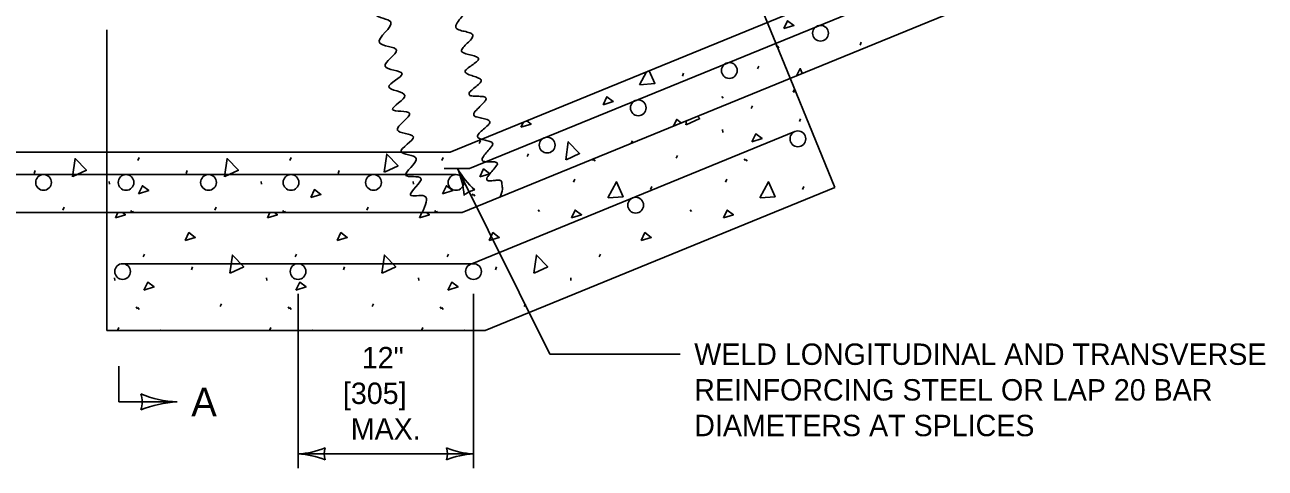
# Model space of a CAD drawing. Extents: x 49991.4 to 50021, y 49987.6 to 50011.4.
# Drawn here: x 50003.206 to 50006.686, y 50002.268 to 50003.512 of the extents above; entities that cross this region are included whole.
import ezdxf

# ---------------------------------------------------------------- set-up
doc = ezdxf.new("R2010")
doc.units = 0
for name, color, linetype in [('Level 1', 7, 'Continuous'), ('Level 2', 7, 'Continuous'), ('Level 3', 7, 'Continuous'), ('Level 4', 7, 'Continuous'), ('Level 6', 7, 'Continuous')]:
    doc.layers.add(name, color=color, linetype=linetype)

msp = doc.modelspace()

# ---------------------------------------------------------------- linework, layer by layer
at = {"layer": 'Level 1'}
for p, q in [((50004.3994, 50003.1543), (50005.8839, 50003.7616)), ((50005.9077, 50003.7036), (50004.4541, 50003.109)), ((50004.4328, 50002.985), (50005.9481, 50003.6048)), ((50005.3138, 50003.4538), (50005.3174, 50003.4485)), ((50005.5492, 50003.4548), (50005.5528, 50003.4628)), ((50005.3184, 50003.4518), (50005.3219, 50003.4465)), ((50005.2614, 50003.388), (50005.265, 50003.396)), ((50005.0509, 50003.3676), (50005.0545, 50003.3756)), ((50005.3533, 50003.3615), (50005.4785, 50003.0556)), ((50005.1619, 50003.3107), (50005.1655, 50003.3054)), ((50005.2442, 50003.2766), (50005.2478, 50003.2846)), ((50005.3792, 50003.2402), (50005.3827, 50003.2482)), ((50005.3666, 50003.2124), (50004.4606, 50002.8417)), ((50005.1639, 50003.2179), (50005.1648, 50003.2099)), ((50004.4807, 50003.1784), (50004.4843, 50003.1864)), ((50004.9075, 50003.1793), (50004.9106, 50003.1864)), ((50002.7761, 50003.1543), (50004.3994, 50003.1543)), ((50004.6157, 50003.142), (50004.6192, 50003.15)), ((50005.0336, 50003.1372), (50005.0372, 50003.1452)), ((50003.5237, 50003.1312), (50003.5273, 50003.1392)), ((50003.9501, 50003.1312), (50003.9536, 50003.1392)), ((50004.3765, 50003.1312), (50004.38, 50003.1392)), ((50004.3823, 50003.109), (50004.4541, 50003.109)), ((50004.799, 50003.1349), (50004.8017, 50003.1309)), ((50004.8027, 50003.1342), (50004.8063, 50003.1289)), ((50005.2245, 50003.1362), (50005.2281, 50003.1309)), ((50005.2291, 50003.1342), (50005.2327, 50003.1289)), ((50002.7761, 50003.0917), (50004.416, 50003.0917)), ((50003.2323, 50003.0948), (50003.2359, 50003.1028)), ((50003.4434, 50003.0725), (50003.4443, 50003.0645)), ((50003.6587, 50003.0948), (50003.6622, 50003.1028)), ((50003.8698, 50003.0725), (50003.8707, 50003.0645)), ((50004.0851, 50003.0948), (50004.0886, 50003.1028)), ((50004.2962, 50003.0725), (50004.2971, 50003.0645)), ((50004.7458, 50003.0704), (50004.7493, 50003.0784)), ((50005.1721, 50003.0704), (50005.1757, 50003.0784)), ((50004.461, 50003.038), (50004.4646, 50003.0327)), ((50004.4656, 50003.036), (50004.4692, 50003.0306)), ((50004.4975, 50002.6543), (50005.4785, 50003.0556)), ((50004.9617, 50003.05), (50004.9652, 50003.058)), ((50005.3881, 50003.05), (50005.3916, 50003.058)), ((50002.7761, 50002.985), (50004.4328, 50002.985)), ((50003.3131, 50002.9918), (50003.3167, 50002.9998)), ((50003.4365, 50002.985), (50003.4365, 50002.6543)), ((50003.504, 50002.9908), (50003.5076, 50002.9855)), ((50003.5086, 50002.9888), (50003.5111, 50002.985)), ((50003.7395, 50002.9918), (50003.743, 50002.9998)), ((50003.9304, 50002.9908), (50003.934, 50002.9855)), ((50003.935, 50002.9888), (50003.9375, 50002.985)), ((50004.1659, 50002.9918), (50004.1694, 50002.9998)), ((50004.3568, 50002.9908), (50004.3604, 50002.9855)), ((50004.3614, 50002.9888), (50004.3639, 50002.985)), ((50004.6463, 50002.9931), (50004.6499, 50002.9878)), ((50005.0727, 50002.9931), (50005.0762, 50002.9878)), ((50003.5387, 50002.8608), (50003.5423, 50002.8688)), ((50003.9651, 50002.8608), (50003.9686, 50002.8688)), ((50004.3915, 50002.8608), (50004.395, 50002.8688)), ((50004.8178, 50002.8608), (50004.8214, 50002.8688)), ((50003.4807, 50002.8417), (50004.4606, 50002.8417)), ((50003.6737, 50002.8244), (50003.6772, 50002.8324)), ((50004.1001, 50002.8244), (50004.1036, 50002.8324)), ((50004.5264, 50002.8244), (50004.53, 50002.8324)), ((50003.4584, 50002.8021), (50003.4593, 50002.7941)), ((50003.8848, 50002.8021), (50003.8857, 50002.7941)), ((50004.3112, 50002.8021), (50004.3121, 50002.7941)), ((50004.7376, 50002.8021), (50004.7384, 50002.7941)), ((50003.7545, 50002.7214), (50003.758, 50002.7294)), ((50004.1809, 50002.7214), (50004.1844, 50002.7294)), ((50004.6072, 50002.7214), (50004.6108, 50002.7294)), ((50003.519, 50002.7204), (50003.5226, 50002.7151)), ((50003.5236, 50002.7184), (50003.5272, 50002.713)), ((50003.9454, 50002.7204), (50003.949, 50002.7151)), ((50003.95, 50002.7184), (50003.9535, 50002.713)), ((50004.3718, 50002.7204), (50004.3754, 50002.7151)), ((50004.3764, 50002.7184), (50004.3799, 50002.713)), ((50003.4365, 50002.6543), (50004.4975, 50002.6543)), ((50003.4666, 50002.6546), (50003.4702, 50002.6626)), ((50003.893, 50002.6546), (50003.8966, 50002.6626)), ((50004.3194, 50002.6546), (50004.323, 50002.6626))]:
    msp.add_line(p, q, dxfattribs=at)
for points in [[(50005.3352, 50003.501), (50005.3459, 50003.5232), (50005.3636, 50003.5099), (50005.3352, 50003.501)], [(50005.3707, 50003.3688), (50005.3814, 50003.3889), (50005.3874, 50003.3756)], [(50004.9311, 50003.3436), (50004.9501, 50003.3796)], [(50004.9578, 50003.3827), (50004.9737, 50003.3471), (50004.9319, 50003.3436)], [(50005.3616, 50003.3224), (50005.3658, 50003.3311)], [(50005.3685, 50003.3245), (50005.3616, 50003.3224)], [(50004.8288, 50003.2876), (50004.8395, 50003.3098), (50004.8572, 50003.2965), (50004.8288, 50003.2876)], [(50005.0263, 50003.2279), (50005.0351, 50003.2464), (50005.0479, 50003.2367)], [(50005.0935, 50003.2553), (50005.0997, 50003.2489), (50005.0617, 50003.2313)], [(50004.6143, 50003.2422), (50004.6265, 50003.233), (50004.5981, 50003.2242)], [(50004.5981, 50003.2242), (50004.6049, 50003.2384)], [(50005.0608, 50003.231), (50005.0624, 50003.2426)], [(50004.7237, 50003.1328), (50004.7308, 50003.1836), (50004.7626, 50003.1507), (50004.7246, 50003.1331)], [(50005.246, 50003.1834), (50005.2566, 50003.2056), (50005.2744, 50003.1923), (50005.246, 50003.1834)], [(50004.2149, 50003.0984), (50004.2219, 50003.1492), (50004.2537, 50003.1163), (50004.2157, 50003.0987)], [(50003.3403, 50003.0856), (50003.3474, 50003.1364), (50003.3792, 50003.1035), (50003.3412, 50003.0859)], [(50003.7667, 50003.0856), (50003.7738, 50003.1364), (50003.8056, 50003.1035), (50003.7676, 50003.0859)], [(50004.4825, 50003.0852), (50004.4931, 50003.1074), (50004.5109, 50003.0941), (50004.4825, 50003.0852)], [(50004.8418, 50003.026), (50004.8658, 50003.0713), (50004.8844, 50003.0295), (50004.8427, 50003.026)], [(50005.2682, 50003.026), (50005.2922, 50003.0713), (50005.3108, 50003.0295), (50005.2691, 50003.026)], [(50003.5255, 50003.038), (50003.5361, 50003.0602), (50003.5539, 50003.0469), (50003.5255, 50003.038)], [(50004.0084, 50003.0271), (50004.019, 50003.0493), (50004.0368, 50003.036), (50004.0084, 50003.0271)], [(50004.3782, 50003.038), (50004.3889, 50003.0602), (50004.4066, 50003.0469), (50004.3782, 50003.038)], [(50003.4604, 50002.97), (50003.4676, 50002.985)], [(50003.4807, 50002.985), (50003.4888, 50002.9789), (50003.4604, 50002.97)], [(50003.8868, 50002.97), (50003.894, 50002.985)], [(50003.9071, 50002.985), (50003.9152, 50002.9789), (50003.8868, 50002.97)], [(50004.3132, 50002.97), (50004.3204, 50002.985)], [(50004.3334, 50002.985), (50004.3416, 50002.9789), (50004.3132, 50002.97)], [(50004.7396, 50002.97), (50004.7502, 50002.9922), (50004.768, 50002.9789), (50004.7396, 50002.97)], [(50005.1659, 50002.97), (50005.1766, 50002.9922), (50005.1943, 50002.9789), (50005.1659, 50002.97)], [(50003.6561, 50002.9066), (50003.6668, 50002.9288), (50003.6845, 50002.9154), (50003.6561, 50002.9066)], [(50004.0825, 50002.9066), (50004.0931, 50002.9288), (50004.1109, 50002.9154), (50004.0825, 50002.9066)], [(50004.5088, 50002.9066), (50004.5195, 50002.9288), (50004.5373, 50002.9154), (50004.5088, 50002.9066)], [(50004.9352, 50002.9066), (50004.9459, 50002.9288), (50004.9636, 50002.9154), (50004.9352, 50002.9066)], [(50003.7817, 50002.8152), (50003.7888, 50002.866), (50003.8206, 50002.8331), (50003.7826, 50002.8155)], [(50004.2081, 50002.8152), (50004.2151, 50002.866), (50004.2469, 50002.8331), (50004.2089, 50002.8155)], [(50004.6345, 50002.8152), (50004.6415, 50002.866), (50004.6733, 50002.8331), (50004.6353, 50002.8155)], [(50003.5405, 50002.7676), (50003.5511, 50002.7898), (50003.5689, 50002.7765), (50003.5405, 50002.7676)], [(50003.9669, 50002.7676), (50003.9775, 50002.7898), (50003.9953, 50002.7765), (50003.9669, 50002.7676)], [(50004.3932, 50002.7676), (50004.4039, 50002.7898), (50004.4216, 50002.7765), (50004.3932, 50002.7676)], [(50003.5861, 50002.6543), (50003.5867, 50002.6555), (50003.5872, 50002.6543)], [(50004.0124, 50002.6543), (50004.013, 50002.6555), (50004.0135, 50002.6543)], [(50004.4388, 50002.6543), (50004.4394, 50002.6555), (50004.4399, 50002.6543)]]:
    msp.add_lwpolyline(points, dxfattribs=at)
for centre in [(50005.4384, 50003.488), (50005.1828, 50003.3834), (50004.9272, 50003.2788), (50005.375, 50003.1919), (50004.6716, 50003.1742), (50003.259, 50003.0696), (50003.4904, 50003.0696), (50003.7218, 50003.0696), (50003.9532, 50003.0696), (50004.1846, 50003.0696), (50004.416, 50003.0696), (50004.92, 50003.0057), (50003.4807, 50002.8196), (50003.9729, 50002.8196), (50004.4651, 50002.8196)]:
    msp.add_circle(centre, 0.0221, dxfattribs=at)
for points in [[(50004.173, 50004.8655), (50004.1642, 50004.8559), (50004.1602, 50004.8397), (50004.1602, 50004.8228), (50004.1622, 50004.8103), (50004.1697, 50004.8052), (50004.184, 50004.8024), (50004.1986, 50004.7996), (50004.204, 50004.7975), (50004.2071, 50004.7944), (50004.2035, 50004.7841), (50004.1908, 50004.7717), (50004.1776, 50004.7595), (50004.1736, 50004.7541), (50004.1728, 50004.7496), (50004.1755, 50004.7464), (50004.181, 50004.744), (50004.1965, 50004.7402), (50004.2121, 50004.7365), (50004.2176, 50004.7342), (50004.2193, 50004.7327), (50004.2203, 50004.7311), (50004.2204, 50004.729), (50004.2154, 50004.7211), (50004.2017, 50004.7087), (50004.1881, 50004.6962), (50004.1841, 50004.6908), (50004.1833, 50004.6862), (50004.1859, 50004.6836), (50004.191, 50004.6821), (50004.2057, 50004.6807), (50004.2203, 50004.6794), (50004.2256, 50004.678), (50004.2282, 50004.6757), (50004.2242, 50004.6661), (50004.2123, 50004.6533), (50004.2005, 50004.6404), (50004.197, 50004.635), (50004.1965, 50004.6308), (50004.1974, 50004.6296), (50004.2044, 50004.6277), (50004.2192, 50004.6275), (50004.2338, 50004.627), (50004.2389, 50004.6256), (50004.2405, 50004.6244), (50004.2414, 50004.6229), (50004.2406, 50004.6183), (50004.2369, 50004.6131), (50004.2244, 50004.6017), (50004.2118, 50004.5903), (50004.208, 50004.5852), (50004.2071, 50004.5807), (50004.208, 50004.5787), (50004.2148, 50004.5732), (50004.2296, 50004.5662), (50004.2443, 50004.5593), (50004.2494, 50004.5556), (50004.2519, 50004.5516), (50004.2471, 50004.5424), (50004.2346, 50004.5319), (50004.2222, 50004.5214), (50004.2184, 50004.5165), (50004.2176, 50004.5121), (50004.2201, 50004.5089), (50004.2252, 50004.5067), (50004.2399, 50004.5038), (50004.2547, 50004.5011), (50004.2599, 50004.499), (50004.2625, 50004.4962), (50004.2585, 50004.4857), (50004.2468, 50004.4723), (50004.235, 50004.459), (50004.2315, 50004.4533), (50004.2308, 50004.4487), (50004.2318, 50004.447), (50004.2394, 50004.4432), (50004.256, 50004.4397), (50004.2725, 50004.436), (50004.2782, 50004.4335), (50004.2801, 50004.432), (50004.281, 50004.4302), (50004.2799, 50004.4261), (50004.2756, 50004.4215), (50004.2614, 50004.4116), (50004.2471, 50004.4018), (50004.2427, 50004.3973), (50004.2414, 50004.3933), (50004.2439, 50004.3898), (50004.2493, 50004.3868), (50004.2651, 50004.3813), (50004.2809, 50004.3758), (50004.2864, 50004.3728), (50004.2889, 50004.3695), (50004.2836, 50004.3607), (50004.2701, 50004.35), (50004.2568, 50004.3391), (50004.2528, 50004.3342), (50004.2519, 50004.33), (50004.2546, 50004.3273), (50004.26, 50004.3257), (50004.2757, 50004.3247), (50004.2913, 50004.3237), (50004.2967, 50004.3221), (50004.2985, 50004.3209), (50004.2994, 50004.3194), (50004.2995, 50004.3172), (50004.2953, 50004.309), (50004.2835, 50004.2958), (50004.2717, 50004.2825), (50004.2683, 50004.2767), (50004.2678, 50004.2719), (50004.2688, 50004.27), (50004.2762, 50004.2654), (50004.2917, 50004.2603), (50004.3072, 50004.2551), (50004.3126, 50004.2519), (50004.3153, 50004.2481), (50004.3112, 50004.2383), (50004.2997, 50004.2268), (50004.288, 50004.2154), (50004.2844, 50004.2103), (50004.2836, 50004.2059), (50004.2861, 50004.2023), (50004.2912, 50004.1993), (50004.3061, 50004.1941), (50004.3209, 50004.1889), (50004.3261, 50004.1858), (50004.3285, 50004.1822), (50004.3284, 50004.18), (50004.3234, 50004.1728), (50004.3101, 50004.1623), (50004.2968, 50004.1519), (50004.2926, 50004.147), (50004.2915, 50004.1426), (50004.294, 50004.1388), (50004.2995, 50004.1354), (50004.3153, 50004.1296), (50004.3311, 50004.1236), (50004.3366, 50004.1202), (50004.339, 50004.1162), (50004.334, 50004.1069), (50004.3217, 50004.0965), (50004.3095, 50004.086), (50004.3057, 50004.0811), (50004.3047, 50004.0766), (50004.3073, 50004.0722), (50004.3128, 50004.0682), (50004.3286, 50004.0609), (50004.3443, 50004.0535), (50004.3497, 50004.0494), (50004.3522, 50004.0449), (50004.3472, 50004.0344), (50004.3348, 50004.0227), (50004.3225, 50004.0109), (50004.3187, 50004.0053), (50004.3179, 50004.0001), (50004.3189, 50003.9974), (50004.3265, 50003.9902), (50004.3428, 50003.9814), (50004.3593, 50003.9728), (50004.3651, 50003.9681), (50004.3681, 50003.9631), (50004.3643, 50003.9516), (50004.3534, 50003.9382), (50004.3425, 50003.9246), (50004.3394, 50003.9184), (50004.339, 50003.913), (50004.3399, 50003.9111), (50004.3463, 50003.907), (50004.3599, 50003.9033), (50004.3736, 50003.8999), (50004.3786, 50003.8976), (50004.3812, 50003.8945), (50004.3777, 50003.8839), (50004.3667, 50003.8708), (50004.3556, 50003.8577), (50004.3525, 50003.8519), (50004.3522, 50003.847), (50004.3532, 50003.8454), (50004.3597, 50003.8419), (50004.3733, 50003.839), (50004.3869, 50003.8362), (50004.3918, 50003.8341), (50004.3944, 50003.8312), (50004.3909, 50003.8184), (50004.3787, 50003.8021), (50004.3664, 50003.7859), (50004.363, 50003.7788), (50004.3628, 50003.7731), (50004.3638, 50003.7715), (50004.3708, 50003.768), (50004.3853, 50003.7654), (50004.3997, 50003.7627), (50004.4049, 50003.7605), (50004.4076, 50003.7573), (50004.4038, 50003.7464), (50004.3921, 50003.7333), (50004.3802, 50003.7204), (50004.3767, 50003.7146), (50004.376, 50003.7098), (50004.3769, 50003.708), (50004.3837, 50003.7032), (50004.3984, 50003.6979), (50004.4131, 50003.6926), (50004.4182, 50003.6895), (50004.4208, 50003.686), (50004.4165, 50003.6775), (50004.4049, 50003.6676), (50004.3933, 50003.6577), (50004.3899, 50003.6531), (50004.3892, 50003.6491), (50004.3918, 50003.646), (50004.397, 50003.6439), (50004.4116, 50003.6411), (50004.4262, 50003.6384), (50004.4314, 50003.6362), (50004.434, 50003.6332), (50004.4303, 50003.6222), (50004.4192, 50003.6084), (50004.4083, 50003.5945), (50004.4052, 50003.5883), (50004.405, 50003.5831), (50004.406, 50003.5813), (50004.4126, 50003.577), (50004.4261, 50003.5726), (50004.4397, 50003.5682), (50004.4446, 50003.5654), (50004.4472, 50003.562), (50004.4436, 50003.5489), (50004.4315, 50003.5328), (50004.4194, 50003.5169), (50004.4159, 50003.5098), (50004.4156, 50003.5039), (50004.4166, 50003.502), (50004.4239, 50003.4975), (50004.4393, 50003.4933), (50004.4547, 50003.4891), (50004.4602, 50003.4864), (50004.4631, 50003.4828), (50004.4593, 50003.4724), (50004.4476, 50003.46), (50004.4358, 50003.4478), (50004.4322, 50003.4424), (50004.4314, 50003.4379), (50004.434, 50003.4345), (50004.4395, 50003.4318), (50004.4552, 50003.4275), (50004.4709, 50003.423), (50004.4763, 50003.4203), (50004.4789, 50003.4168), (50004.4788, 50003.4148), (50004.4738, 50003.4081), (50004.4605, 50003.3983), (50004.4472, 50003.3885), (50004.443, 50003.384), (50004.4419, 50003.3799), (50004.4443, 50003.3764), (50004.4494, 50003.3733), (50004.4643, 50003.3678), (50004.4792, 50003.3624), (50004.4843, 50003.3594), (50004.4868, 50003.3561), (50004.482, 50003.3472), (50004.4694, 50003.3365), (50004.457, 50003.3256), (50004.4533, 50003.3207), (50004.4525, 50003.3165), (50004.4552, 50003.3137), (50004.4606, 50003.3121), (50004.4762, 50003.3111), (50004.4918, 50003.3101), (50004.4973, 50003.3086), (50004.4991, 50003.3075), (50004.5, 50003.306), (50004.5001, 50003.3038), (50004.4955, 50003.2956), (50004.4828, 50003.2823), (50004.4701, 50003.269), (50004.4663, 50003.2632), (50004.4657, 50003.2585), (50004.4666, 50003.2569), (50004.4735, 50003.2532), (50004.4882, 50003.2495), (50004.5029, 50003.2457), (50004.5081, 50003.2432), (50004.5106, 50003.24), (50004.506, 50003.2304), (50004.4933, 50003.219), (50004.4807, 50003.2075), (50004.477, 50003.2023), (50004.4763, 50003.1978), (50004.4772, 50003.1962), (50004.4836, 50003.1922), (50004.4973, 50003.1883), (50004.5111, 50003.1845), (50004.516, 50003.1822), (50004.5185, 50003.1793), (50004.5149, 50003.169), (50004.5038, 50003.1557), (50004.4928, 50003.1423), (50004.4898, 50003.1365), (50004.4895, 50003.1318), (50004.4904, 50003.1304), (50004.4969, 50003.128), (50004.5105, 50003.1274), (50004.5241, 50003.1269), (50004.529, 50003.1259), (50004.5317, 50003.1239), (50004.5281, 50003.114), (50004.5164, 50003.1004), (50004.5051, 50003.0866), (50004.5022, 50003.0809), (50004.5026, 50003.0764), (50004.5102, 50003.074), (50004.5228, 50003.0749), (50004.5352, 50003.0759), (50004.5397, 50003.0754), (50004.5422, 50003.0737), (50004.5449, 50003.0646), (50004.5463, 50003.0509), (50004.5391, 50003.0285)], [(50003.9597, 50004.8236), (50003.9479, 50004.7679), (50003.9928, 50004.752), (50003.9585, 50004.7072), (50004.006, 50004.6887), (50003.969, 50004.6438), (50004.0139, 50004.6333), (50003.9822, 50004.5884), (50004.0271, 50004.5805), (50003.9928, 50004.5383), (50004.0376, 50004.5092), (50004.0033, 50004.4697), (50004.0482, 50004.4538), (50004.0165, 50004.4063), (50004.0667, 50004.3878), (50004.0271, 50004.3509), (50004.0746, 50004.3271), (50004.0376, 50004.2876), (50004.0851, 50004.277), (50004.0535, 50004.2295), (50004.101, 50004.2057), (50004.0693, 50004.1635), (50004.1142, 50004.1398), (50004.0772, 50004.1002), (50004.1247, 50004.0738), (50004.0904, 50004.0342), (50004.1379, 50004.0025), (50004.1036, 50003.9577), (50004.1538, 50003.9207), (50004.1247, 50003.8706), (50004.1669, 50003.8521), (50004.1379, 50003.8046), (50004.1801, 50003.7888), (50004.1485, 50003.7307), (50004.1933, 50003.7149), (50004.1617, 50003.6674), (50004.2065, 50003.6436), (50004.1749, 50003.6067), (50004.2197, 50003.5908), (50004.1907, 50003.5407), (50004.2329, 50003.5196), (50004.2013, 50003.4615), (50004.2488, 50003.4404), (50004.2171, 50003.3955), (50004.2646, 50003.3744), (50004.2276, 50003.3375), (50004.2725, 50003.3137), (50004.2382, 50003.2741), (50004.2857, 50003.2636), (50004.2514, 50003.2161), (50004.2963, 50003.1976), (50004.262, 50003.1554), (50004.3042, 50003.1369), (50004.2752, 50003.0894), (50004.3174, 50003.0815), (50004.2883, 50003.034), (50004.3279, 50003.0313), (50004.3212, 50002.985)]]:
    msp.add_spline(points, degree=3, dxfattribs=at)
at = {"layer": 'Level 3'}
for p, q in [((50004.4198, 50003.109), (50004.6791, 50002.5879)), ((50003.9729, 50002.7575), (50003.9729, 50002.2682)), ((50004.4651, 50002.7575), (50004.4651, 50002.2682)), ((50005.0443, 50002.5879), (50004.6791, 50002.5879)), ((50003.9729, 50002.3082), (50004.4651, 50002.3082))]:
    msp.add_line(p, q, dxfattribs=at)
for centre, radius, start, end in [((50004.2168, 50003.0182), 0.2223, 3.911, 24.0945), ((50004.623, 50003.223), 0.233, 209.2823, 228.5322), ((50004.4769, 50002.9942), 0.0548, 98.5938, 134.3162), ((50003.6457, 50002.7502), 0.2964, 247.456, 267.6395), ((50003.4625, 50002.454), 0.073, 342.1388, 17.8612), ((50003.6488, 50002.1437), 0.3107, 92.8273, 112.0772), ((50003.9614, 50002.5409), 0.233, 272.8273, 292.0772), ((50003.9637, 50002.0861), 0.2223, 67.456, 87.6395), ((50004.1011, 50002.3082), 0.0548, 162.1388, 197.8612), ((50004.4743, 50002.5303), 0.2223, 247.456, 267.6395), ((50004.3369, 50002.3082), 0.0548, 342.1388, 17.8612), ((50004.4766, 50002.0755), 0.233, 92.8273, 112.0772)]:
    msp.add_arc(centre, radius, start, end, dxfattribs=at)
at = {"layer": 'Level 4'}
for p, q in [((50005.1047, 50003.9695), (50005.3533, 50003.3615)), ((50003.4365, 50003.4974), (50003.4365, 50002.985))]:
    msp.add_line(p, q, dxfattribs=at)
at = {"layer": 'Level 6'}
for p, q in [((50003.4705, 50002.5543), (50003.4705, 50002.454)), ((50003.4705, 50002.454), (50003.6335, 50002.454))]:
    msp.add_line(p, q, dxfattribs=at)

# ---------------------------------------------------------------- texts
at = {"layer": 'Level 2'}
for s, height, p in [('WELD LONGITUDINAL AND TRANSVERSE ', 0.06, (50005.0843, 50002.5579)), ('12"', 0.06, (50004.1517, 50002.5482)), ('REINFORCING STEEL OR LAP 20 BAR', 0.06, (50005.0843, 50002.4579)), ('A', 0.08, (50003.6735, 50002.414)), ('[305]', 0.06, (50004.0988, 50002.4482)), ('DIAMETERS AT SPLICES', 0.06, (50005.0843, 50002.3579)), ('MAX.', 0.06, (50004.1208, 50002.3482))]:
    msp.add_text(s, height=height, dxfattribs=at).set_placement(p)

doc.saveas('drawing.dxf')
